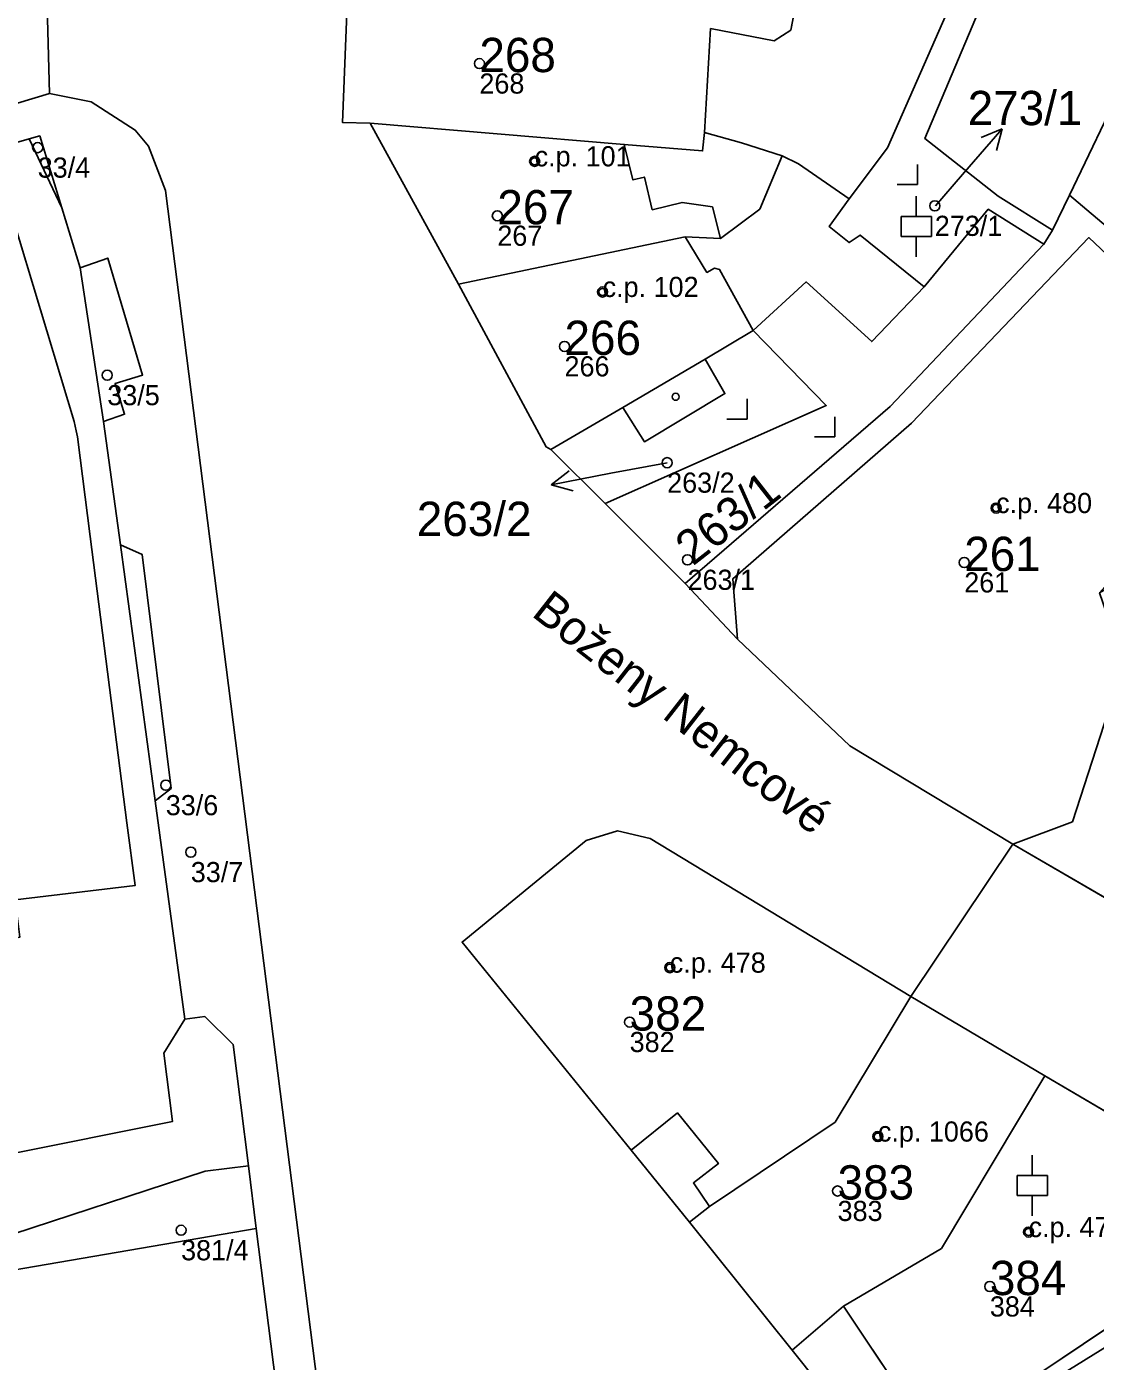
# Model space of a CAD drawing. Extents: x -878211 to -870363, y -1058464 to -1052522.
# Drawn here: x -874484.1 to -874431.2, y -1056253.8 to -1056187.6 of the extents above; entities that cross this region are included whole.
import ezdxf

# ---------------------------------------------------------------- set-up
doc = ezdxf.new("R2010")
doc.units = 0
for name, color, linetype in [('Vrstva 1', 7, 'Continuous'), ('Vrstva 2', 7, 'Continuous'), ('Vrstva 3', 7, 'Continuous'), ('Vrstva 4', 7, 'Continuous'), ('Vrstva 5', 7, 'Continuous'), ('Vrstva 50', 7, 'Continuous'), ('Vrstva 51', 7, 'Continuous'), ('Vrstva 52', 7, 'Continuous'), ('Vrstva 7', 7, 'Continuous')]:
    doc.layers.add(name, color=color, linetype=linetype)

msp = doc.modelspace()

# ---------------------------------------------------------------- linework, layer by layer
at = {"layer": 'Vrstva 1'}
for p, q in [((-874436.76, -1056186.38), (-874439.61, -1056193.1)), ((-874462.72, -1056200.33), (-874467.1, -1056192.35)), ((-874432.43, -1056195.91), (-874433.27, -1056197.66)), ((-874433.27, -1056197.66), (-874433.7, -1056198.35)), ((-874458.14, -1056208.53), (-874455.45, -1056211.22)), ((-874455.45, -1056211.22), (-874451.49, -1056215.18)), ((-874440.29, -1056235.67), (-874435.24, -1056228.11)), ((-874435.24, -1056228.11), (-874428.88, -1056231.82)), ((-874433.66, -1056239.6), (-874440.29, -1056235.67)), ((-874424.98, -1056244.72), (-874433.66, -1056239.6)), ((-874451.28, -1056246.86), (-874450.28, -1056246.09)), ((-874451.28, -1056246.86), (-874446.18, -1056253.22)), ((-874446.18, -1056253.22), (-874443.63, -1056251.04))]:
    msp.add_line(p, q, dxfattribs=at)
for points in [[(-874432.43, -1056195.91), (-874429.74, -1056190.29), (-874425.58, -1056178.53)], [(-874467.1, -1056192.35), (-874468.47, -1056192.32), (-874468.14, -1056183.93)], [(-874438.19, -1056186.12), (-874441.45, -1056193.57), (-874443.36, -1056196.1)], [(-874471.27, -1056258.91), (-874469.25, -1056258.58), (-874477.25, -1056195.68), (-874478.09, -1056193.48), (-874478.75, -1056192.69), (-874480.94, -1056191.28), (-874483, -1056190.87)], [(-874446.68, -1056193.96), (-874448.7, -1056193.33), (-874450.53, -1056192.81), (-874450.62, -1056193.72), (-874454.51, -1056193.4), (-874467.1, -1056192.35)], [(-874439.61, -1056193.1), (-874435.97, -1056195.97), (-874433.27, -1056197.66)], [(-874446.68, -1056193.96), (-874447.79, -1056196.62), (-874449.74, -1056198.07), (-874451.49, -1056197.99), (-874462.72, -1056200.33)], [(-874443.36, -1056196.1), (-874445.86, -1056194.37), (-874446.68, -1056193.96)], [(-874439.63, -1056200.46), (-874442.81, -1056197.9), (-874443.35, -1056198.27), (-874444.35, -1056197.47), (-874443.36, -1056196.1)], [(-874425.24, -1056212.37), (-874423.66, -1056203.35), (-874432.43, -1056195.91)], [(-874433.7, -1056198.35), (-874436.46, -1056196.62), (-874439.63, -1056200.46)], [(-874433.7, -1056198.35), (-874441.33, -1056206.41), (-874451.49, -1056215.18)], [(-874462.72, -1056200.33), (-874458.38, -1056208.41), (-874458.14, -1056208.53)], [(-874439.63, -1056200.46), (-874442.24, -1056203.18), (-874445.48, -1056200.22), (-874448.11, -1056202.63)], [(-874448.11, -1056202.63), (-874450.5, -1056204.05), (-874449.52, -1056205.76), (-874453.51, -1056208.15), (-874454.58, -1056206.45), (-874458.14, -1056208.53)], [(-874448.11, -1056202.63), (-874444.49, -1056206.35), (-874455.45, -1056211.22)], [(-874435.24, -1056228.11), (-874432.29, -1056227), (-874429.74, -1056219.15), (-874430.94, -1056215.65), (-874425.24, -1056212.37)], [(-874451.49, -1056215.18), (-874448.89, -1056217.95), (-874443.32, -1056223.23), (-874435.24, -1056228.11)], [(-874440.29, -1056235.67), (-874453.22, -1056227.84), (-874454.85, -1056227.45), (-874456.4, -1056227.93), (-874462.55, -1056232.97), (-874454.17, -1056243.3), (-874451.28, -1056246.86)], [(-874450.28, -1056246.09), (-874444.05, -1056241.9), (-874440.29, -1056235.67)], [(-874443.63, -1056251.04), (-874438.77, -1056248.17), (-874433.66, -1056239.6)], [(-874446.18, -1056253.22), (-874442.39, -1056257.96), (-874444.37, -1056258.78), (-874443.91, -1056259.34), (-874433.6, -1056254.9), (-874426.69, -1056250.62), (-874424.25, -1056247.03), (-874424.37, -1056244.01)]]:
    msp.add_lwpolyline(points, dxfattribs=at)
at = {"layer": 'Vrstva 3'}
for p, q in [((-874439.97, -1056195.39), (-874439.97, -1056194.39)), ((-874440.971, -1056195.39), (-874439.97, -1056195.39)), ((-874440.03, -1056196.971), (-874440.03, -1056195.97)), ((-874440.781, -1056196.971), (-874439.279, -1056196.971)), ((-874440.781, -1056197.972), (-874440.781, -1056196.971)), ((-874439.279, -1056197.972), (-874439.279, -1056196.971)), ((-874440.781, -1056197.972), (-874439.279, -1056197.972)), ((-874440.03, -1056198.97), (-874440.03, -1056197.972)), ((-874448.42, -1056207.03), (-874448.42, -1056206.03)), ((-874449.421, -1056207.03), (-874448.42, -1056207.03)), ((-874444.07, -1056207.91), (-874444.07, -1056206.91)), ((-874445.071, -1056207.91), (-874444.07, -1056207.91)), ((-874434.28, -1056244.551), (-874434.28, -1056243.55)), ((-874435.031, -1056244.551), (-874433.529, -1056244.551)), ((-874435.031, -1056245.552), (-874435.031, -1056244.551)), ((-874433.529, -1056245.552), (-874433.529, -1056244.551)), ((-874435.031, -1056245.552), (-874433.529, -1056245.552)), ((-874434.28, -1056246.55), (-874434.28, -1056245.552))]:
    msp.add_line(p, q, dxfattribs=at)
at = {"layer": 'Vrstva 4'}
for p, q in [((-874445.67, -1056184.74), (-874446.25, -1056187.73)), ((-874450.23, -1056187.65), (-874450.53, -1056192.81)), ((-874447.07, -1056188.26), (-874450.23, -1056187.65)), ((-874446.25, -1056187.73), (-874447.07, -1056188.26)), ((-874454.51, -1056193.4), (-874454.08, -1056195.16)), ((-874454.08, -1056195.16), (-874453.51, -1056195.02)), ((-874453.51, -1056195.02), (-874453.12, -1056196.64)), ((-874453.12, -1056196.64), (-874451.64, -1056196.28)), ((-874450.14, -1056196.5), (-874451.64, -1056196.28)), ((-874449.74, -1056198.07), (-874450.14, -1056196.5)), ((-874451.49, -1056197.99), (-874450.41, -1056199.75)), ((-874440.26, -1056207.23), (-874431.48, -1056198.02)), ((-874431.48, -1056198.02), (-874425.45, -1056203.7)), ((-874450.03, -1056199.54), (-874450.41, -1056199.75)), ((-874449.78, -1056199.61), (-874450.03, -1056199.54)), ((-874448.11, -1056202.63), (-874449.78, -1056199.61)), ((-874454.58, -1056206.45), (-874450.5, -1056204.05)), ((-874449.12, -1056214.95), (-874440.26, -1056207.23)), ((-874448.89, -1056217.95), (-874449.12, -1056214.95)), ((-874454.17, -1056243.3), (-874451.87, -1056241.45)), ((-874451.87, -1056241.45), (-874449.84, -1056243.96)), ((-874449.84, -1056243.96), (-874451.08, -1056244.92)), ((-874451.08, -1056244.92), (-874450.28, -1056246.09)), ((-874433.85, -1056254.32), (-874427.45, -1056250.02)), ((-874443.63, -1056251.04), (-874439.75, -1056256.85))]:
    msp.add_line(p, q, dxfattribs=at)
at = {"layer": 'Vrstva 5'}
for centre in [(-874458.9568, -1056194.23916), (-874455.5868, -1056200.71916), (-874451.9568, -1056205.91916), (-874436.0768, -1056211.43916), (-874452.2568, -1056234.23916), (-874441.9368, -1056242.61916), (-874434.4668, -1056247.35916)]:
    msp.add_circle(centre, 0.175, dxfattribs=at)
at = {"layer": 'Vrstva 50'}
for centre in [(-874461.69, -1056189.38994), (-874483.59, -1056193.55994), (-874458.95, -1056194.23994), (-874439.11, -1056196.44994), (-874460.8, -1056196.93994), (-874455.58, -1056200.71994), (-874457.47, -1056203.41994), (-874480.14, -1056204.84994), (-874452.38, -1056209.18994), (-874436.07, -1056211.43994), (-874451.37, -1056214.00994), (-874437.65, -1056214.13994), (-874477.24, -1056225.18994), (-874476, -1056228.50994), (-874452.25, -1056234.23994), (-874454.24, -1056236.93994), (-874441.93, -1056242.61994), (-874443.93, -1056245.31994), (-874476.48, -1056247.26994), (-874434.46, -1056247.35994), (-874436.38, -1056250.05994)]:
    msp.add_circle(centre, 0.25, dxfattribs=at)
at = {"layer": 'Vrstva 51'}
for points in [[(-874486.45, -1056151.47), (-874484.09, -1056153.86), (-874481.73, -1056157.59), (-874480.67, -1056160.29), (-874479.15, -1056165.45), (-874478.62, -1056171.66), (-874478.87, -1056177.09), (-874478.9, -1056180.66), (-874479.34, -1056182.37), (-874481.33, -1056184.27), (-874483.16, -1056185.29), (-874483, -1056190.87), (-874480.94, -1056191.28), (-874478.75, -1056192.69), (-874478.09, -1056193.48), (-874477.25, -1056195.68), (-874469.25, -1056258.58)], [(-874442.39, -1056257.96), (-874446.18, -1056253.22), (-874451.28, -1056246.86), (-874454.17, -1056243.3), (-874462.55, -1056232.97), (-874456.4, -1056227.93), (-874454.85, -1056227.45), (-874453.22, -1056227.84), (-874440.29, -1056235.67), (-874435.24, -1056228.11), (-874443.32, -1056223.23), (-874448.89, -1056217.95), (-874451.49, -1056215.18), (-874455.45, -1056211.22), (-874458.14, -1056208.53), (-874458.38, -1056208.41), (-874462.72, -1056200.33), (-874467.1, -1056192.35), (-874468.47, -1056192.32), (-874468.14, -1056183.93)], [(-874517.61, -1056201.33), (-874483, -1056190.87), (-874483.16, -1056185.29), (-874487.04, -1056186.81)], [(-874429.74, -1056190.29), (-874432.43, -1056195.91), (-874423.66, -1056203.35)], [(-874469.25, -1056258.58), (-874477.25, -1056195.68), (-874478.09, -1056193.48), (-874478.75, -1056192.69), (-874480.94, -1056191.28), (-874483, -1056190.87), (-874517.61, -1056201.33)], [(-874485.86, -1056193.66), (-874484.02, -1056193.13), (-874483.49, -1056192.98), (-874482.4, -1056196.54), (-874481.49, -1056199.53), (-874480.12, -1056199.04), (-874478.39, -1056204.84), (-874479.75, -1056205.26), (-874479.28, -1056206.79), (-874480.32, -1056207.15), (-874479.49, -1056213.27), (-874478.41, -1056213.75), (-874476.97, -1056225.35), (-874477.76, -1056225.97), (-874476.29, -1056236.8), (-874475.31, -1056236.66), (-874473.9, -1056238.06), (-874473.14, -1056244.07), (-874472.75, -1056247.18), (-874471.42, -1056257.72)], [(-874429.74, -1056219.15), (-874432.29, -1056227), (-874435.24, -1056228.11), (-874428.88, -1056231.82)], [(-874422.29, -1056256.77), (-874408.34, -1056241.77), (-874412.93, -1056235.4), (-874418.74, -1056237.49), (-874424.37, -1056244.01), (-874424.25, -1056247.03), (-874426.69, -1056250.62), (-874433.6, -1056254.9)]]:
    msp.add_lwpolyline(points, dxfattribs=at)
for points in [[(-874435.56, -1056183.54), (-874436.76, -1056186.38), (-874439.61, -1056193.1), (-874435.97, -1056195.97), (-874433.27, -1056197.66), (-874432.43, -1056195.91), (-874429.74, -1056190.29), (-874425.58, -1056178.53), (-874428.66, -1056176.17), (-874432.41, -1056174.98)], [(-874438.19, -1056186.12), (-874445.67, -1056184.74), (-874450.05, -1056184.02), (-874468.14, -1056183.93), (-874468.47, -1056192.32), (-874467.1, -1056192.35), (-874454.51, -1056193.4), (-874450.62, -1056193.72), (-874450.53, -1056192.81), (-874448.7, -1056193.33), (-874446.68, -1056193.96), (-874445.86, -1056194.37), (-874443.36, -1056196.1), (-874441.45, -1056193.57)], [(-874441.45, -1056193.57), (-874443.36, -1056196.1), (-874444.35, -1056197.47), (-874443.35, -1056198.27), (-874442.81, -1056197.9), (-874439.63, -1056200.46), (-874436.46, -1056196.62), (-874433.7, -1056198.35), (-874433.27, -1056197.66), (-874435.97, -1056195.97), (-874439.61, -1056193.1), (-874436.76, -1056186.38), (-874438.19, -1056186.12)], [(-874454.51, -1056193.4), (-874467.1, -1056192.35), (-874462.72, -1056200.33), (-874451.49, -1056197.99), (-874449.74, -1056198.07), (-874447.79, -1056196.62), (-874446.68, -1056193.96), (-874448.7, -1056193.33), (-874450.53, -1056192.81), (-874450.62, -1056193.72)], [(-874496.93, -1056240.45), (-874494.41, -1056241.87), (-874493.67, -1056245.23), (-874476.91, -1056241.88), (-874477.34, -1056238.48), (-874476.29, -1056236.8), (-874477.76, -1056225.97), (-874479.49, -1056213.27), (-874480.32, -1056207.15), (-874481.49, -1056199.53), (-874482.4, -1056196.54), (-874484.02, -1056193.13), (-874485.86, -1056193.66), (-874508.37, -1056200.53), (-874506.29, -1056210.58), (-874505.47, -1056214.67), (-874504.65, -1056218.66), (-874504.51, -1056219.35), (-874503.85, -1056219.27), (-874500.77, -1056235.84), (-874496.81, -1056236.4)], [(-874482.4, -1056196.54), (-874483.49, -1056192.98), (-874484.02, -1056193.13)], [(-874451.49, -1056197.99), (-874462.72, -1056200.33), (-874458.38, -1056208.41), (-874458.14, -1056208.53), (-874454.58, -1056206.45), (-874453.51, -1056208.15), (-874449.52, -1056205.76), (-874450.5, -1056204.05), (-874448.11, -1056202.63), (-874445.48, -1056200.22), (-874442.24, -1056203.18), (-874439.63, -1056200.46), (-874442.81, -1056197.9), (-874443.35, -1056198.27), (-874444.35, -1056197.47), (-874443.36, -1056196.1), (-874445.86, -1056194.37), (-874446.68, -1056193.96), (-874447.79, -1056196.62), (-874449.74, -1056198.07)], [(-874429.74, -1056219.15), (-874430.94, -1056215.65), (-874425.24, -1056212.37), (-874423.66, -1056203.35), (-874432.43, -1056195.91), (-874433.27, -1056197.66), (-874433.7, -1056198.35), (-874441.33, -1056206.41), (-874451.49, -1056215.18), (-874448.89, -1056217.95), (-874443.32, -1056223.23), (-874435.24, -1056228.11), (-874432.29, -1056227)], [(-874448.11, -1056202.63), (-874444.49, -1056206.35), (-874455.45, -1056211.22), (-874451.49, -1056215.18), (-874441.33, -1056206.41), (-874433.7, -1056198.35), (-874436.46, -1056196.62), (-874439.63, -1056200.46), (-874442.24, -1056203.18), (-874445.48, -1056200.22)], [(-874479.75, -1056205.26), (-874478.39, -1056204.84), (-874480.12, -1056199.04), (-874481.49, -1056199.53), (-874480.32, -1056207.15), (-874479.28, -1056206.79)], [(-874454.58, -1056206.45), (-874458.14, -1056208.53), (-874455.45, -1056211.22), (-874444.49, -1056206.35), (-874448.11, -1056202.63), (-874450.5, -1056204.05), (-874449.52, -1056205.76), (-874453.51, -1056208.15)], [(-874479.49, -1056213.27), (-874477.76, -1056225.97), (-874476.97, -1056225.35), (-874478.41, -1056213.75)], [(-874462.55, -1056232.97), (-874454.17, -1056243.3), (-874451.28, -1056246.86), (-874450.28, -1056246.09), (-874444.05, -1056241.9), (-874440.29, -1056235.67), (-874453.22, -1056227.84), (-874454.85, -1056227.45), (-874456.4, -1056227.93)], [(-874422.49, -1056238.33), (-874423.27, -1056237.96), (-874423.16, -1056237.73), (-874426.7, -1056234.92), (-874428.88, -1056231.82), (-874435.24, -1056228.11), (-874440.29, -1056235.67), (-874433.66, -1056239.6), (-874424.98, -1056244.72), (-874424.37, -1056244.01), (-874418.74, -1056237.49), (-874422.26, -1056238.13)], [(-874446.18, -1056253.22), (-874443.63, -1056251.04), (-874438.77, -1056248.17), (-874433.66, -1056239.6), (-874440.29, -1056235.67), (-874444.05, -1056241.9), (-874450.28, -1056246.09), (-874451.28, -1056246.86)], [(-874475.29, -1056244.34), (-874473.14, -1056244.07), (-874473.9, -1056238.06), (-874475.31, -1056236.66), (-874476.29, -1056236.8), (-874477.34, -1056238.48), (-874476.91, -1056241.88), (-874493.67, -1056245.23), (-874494.41, -1056241.87), (-874496.93, -1056240.45), (-874497.25, -1056251.52), (-874496.29, -1056251.21)], [(-874424.98, -1056244.72), (-874433.66, -1056239.6), (-874438.77, -1056248.17), (-874443.63, -1056251.04), (-874446.18, -1056253.22), (-874442.39, -1056257.96), (-874444.37, -1056258.78), (-874443.91, -1056259.34), (-874433.6, -1056254.9), (-874426.69, -1056250.62), (-874424.25, -1056247.03), (-874424.37, -1056244.01)], [(-874472.75, -1056247.18), (-874473.14, -1056244.07), (-874475.29, -1056244.34), (-874496.29, -1056251.21)], [(-874472.75, -1056247.18), (-874496.29, -1056251.21), (-874497.25, -1056251.52), (-874501.14, -1056253.07), (-874511.47, -1056254.46), (-874511.26, -1056267.37), (-874502.78, -1056264.06), (-874471.42, -1056257.72)]]:
    msp.add_lwpolyline(points, close=True, dxfattribs=at)
at = {"layer": 'Vrstva 52'}
for points in [[(-874446.25, -1056187.73), (-874445.67, -1056184.74), (-874450.05, -1056184.02), (-874468.14, -1056183.93), (-874468.47, -1056192.32), (-874467.1, -1056192.35), (-874454.51, -1056193.4), (-874450.62, -1056193.72), (-874450.53, -1056192.81), (-874450.23, -1056187.65), (-874447.07, -1056188.26)], [(-874449.74, -1056198.07), (-874450.14, -1056196.5), (-874451.64, -1056196.28), (-874453.12, -1056196.64), (-874453.51, -1056195.02), (-874454.08, -1056195.16), (-874454.51, -1056193.4), (-874467.1, -1056192.35), (-874462.72, -1056200.33), (-874451.49, -1056197.99)], [(-874506.29, -1056210.58), (-874505.47, -1056214.67), (-874499.11, -1056212.82), (-874495.64, -1056214.8), (-874495.19, -1056218.22), (-874493.22, -1056233.88), (-874493.64, -1056233.95), (-874493.55, -1056234.46), (-874484.48, -1056232.73), (-874484.7, -1056230.87), (-874478.76, -1056230.17), (-874479.17, -1056227.06), (-874480.99, -1056212.85), (-874481.62, -1056207.9), (-874481.69, -1056207.61), (-874481.78, -1056207.15), (-874485.86, -1056193.66), (-874508.37, -1056200.53)], [(-874462.72, -1056200.33), (-874458.38, -1056208.41), (-874458.14, -1056208.53), (-874454.58, -1056206.45), (-874450.5, -1056204.05), (-874448.11, -1056202.63), (-874449.78, -1056199.61), (-874450.03, -1056199.54), (-874450.41, -1056199.75), (-874451.49, -1056197.99)], [(-874432.29, -1056227), (-874429.74, -1056219.15), (-874430.94, -1056215.65), (-874429.19, -1056213.68), (-874429.26, -1056212.64), (-874425.24, -1056212.37), (-874425.22, -1056211.24), (-874425.45, -1056203.7), (-874431.48, -1056198.02), (-874440.26, -1056207.23), (-874449.12, -1056214.95), (-874448.89, -1056217.95), (-874443.32, -1056223.23), (-874435.24, -1056228.11)], [(-874456.4, -1056227.93), (-874462.55, -1056232.97), (-874454.17, -1056243.3), (-874451.87, -1056241.45), (-874449.84, -1056243.96), (-874451.08, -1056244.92), (-874450.28, -1056246.09), (-874444.05, -1056241.9), (-874440.29, -1056235.67), (-874453.22, -1056227.84), (-874454.85, -1056227.45)], [(-874450.28, -1056246.09), (-874451.28, -1056246.86), (-874446.18, -1056253.22), (-874443.63, -1056251.04), (-874438.77, -1056248.17), (-874433.66, -1056239.6), (-874440.29, -1056235.67), (-874444.05, -1056241.9)], [(-874443.63, -1056251.04), (-874439.75, -1056256.85), (-874433.85, -1056254.32), (-874427.45, -1056250.02), (-874424.95, -1056246.8), (-874424.98, -1056244.72), (-874433.66, -1056239.6), (-874438.77, -1056248.17)]]:
    msp.add_lwpolyline(points, close=True, dxfattribs=at)
at = {"layer": 'Vrstva 7'}
for p, q in [((-874437.74, -1056194.89), (-874435.771, -1056192.625)), ((-874435.771, -1056192.625), (-874436.806, -1056193.052)), ((-874435.771, -1056192.625), (-874436.05, -1056193.709)), ((-874439.07, -1056196.45), (-874437.74, -1056194.89)), ((-874458.126, -1056210.283), (-874457.238, -1056209.6)), ((-874455.18, -1056209.71), (-874458.126, -1056210.283)), ((-874452.38, -1056209.19), (-874455.18, -1056209.71)), ((-874458.126, -1056210.283), (-874457.047, -1056210.583))]:
    msp.add_line(p, q, dxfattribs=at)

# ---------------------------------------------------------------- texts
at = {"layer": 'Vrstva 2'}
for s, p in [('268', (-874461.69, -1056189.814)), ('273/1', (-874437.48, -1056192.445)), ('267', (-874460.8, -1056197.365)), ('266', (-874457.47, -1056203.844)), ('263/2', (-874464.792, -1056212.825)), ('261', (-874437.65, -1056214.564)), ('382', (-874454.24, -1056237.365)), ('383', (-874443.93, -1056245.745)), ('384', (-874436.38, -1056250.485))]:
    msp.add_text(s, height=1.699998, dxfattribs=at).set_placement(p)
msp.add_text('263/1', height=1.699998, rotation=38, dxfattribs=at).set_placement((-874451.108, -1056214.344))
at = {"layer": 'Vrstva 50'}
for s, p in [('268', (-874461.69, -1056190.879)), ('c.p. 101', (-874458.95, -1056194.49)), ('33/4', (-874483.59, -1056195.049)), ('273/1', (-874439.11, -1056197.939)), ('267', (-874460.8, -1056198.429)), ('c.p. 102', (-874455.58, -1056200.97)), ('266', (-874457.47, -1056204.909)), ('33/5', (-874480.14, -1056206.339)), ('263/2', (-874452.38, -1056210.679)), ('c.p. 480', (-874436.07, -1056211.69)), ('263/1', (-874451.37, -1056215.499)), ('261', (-874437.65, -1056215.629)), ('33/6', (-874477.24, -1056226.679)), ('33/7', (-874476, -1056229.999)), ('c.p. 478', (-874452.25, -1056234.49)), ('382', (-874454.24, -1056238.429)), ('c.p. 1066', (-874441.93, -1056242.87)), ('383', (-874443.93, -1056246.809)), ('c.p. 476', (-874434.46, -1056247.61)), ('381/4', (-874476.48, -1056248.759)), ('384', (-874436.38, -1056251.549))]:
    msp.add_text(s, height=0.999996, dxfattribs=at).set_placement(p)
at = {"layer": 'Vrstva 7'}
msp.add_text('Boženy Nemcové', height=1.699998, rotation=321.9999972, dxfattribs=at).set_placement((-874459.161, -1056216.754))

doc.saveas('drawing.dxf')
